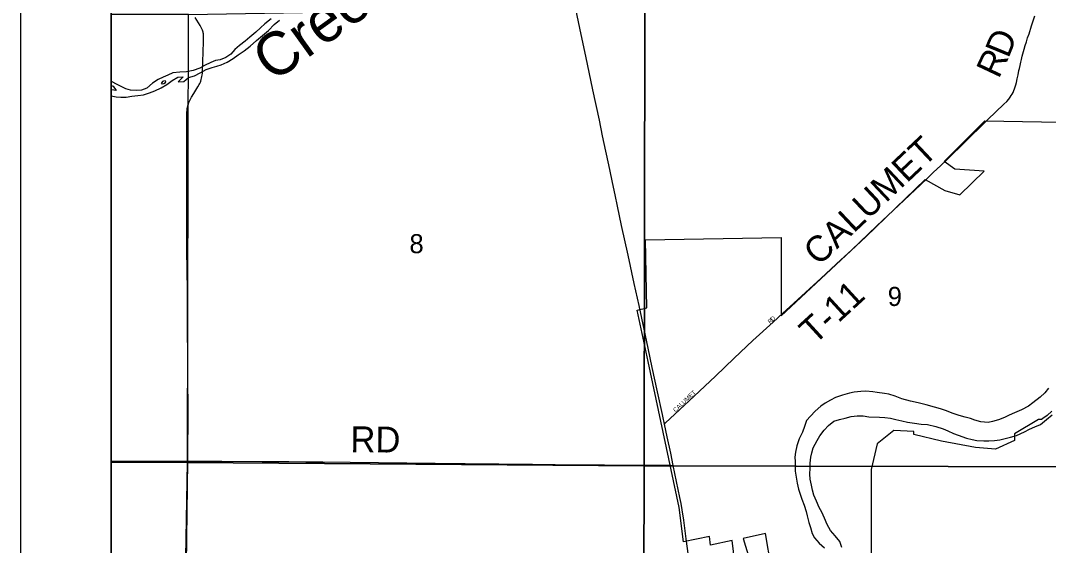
# Model space of a CAD drawing. Extents: x 0 to 680, y 0 to 440.
# Drawn here: x 341.54 to 381.29, y 256.36 to 276.66 of the extents above; entities that cross this region are included whole.
import ezdxf

# ---------------------------------------------------------------- set-up
doc = ezdxf.new("R2010")
doc.units = 0
for name, color, linetype in [('GM_X_Adjacent_County', 7, 'Continuous'), ('GM_X_City_Street', 7, 'Continuous'), ('GM_X_City_Street_Text', 7, 'Continuous'), ('GM_X_Corporation', 7, 'Continuous'), ('GM_X_County', 7, 'Continuous'), ('GM_X_Major_River', 7, 'Continuous'), ('GM_X_Minor_River', 7, 'Continuous'), ('GM_X_Minor_River_Text', 7, 'Continuous'), ('GM_X_Section', 7, 'Continuous'), ('GM_X_Section_Text', 7, 'Continuous'), ('GM_X_State_Route', 7, 'Continuous'), ('GM_X_Township', 7, 'Continuous'), ('GM_X_Township_Road', 7, 'Continuous'), ('GM_X_Township_Road_Text', 7, 'Continuous'), ('SH_Data', 7, 'Continuous'), ('SH_Text', 7, 'Continuous')]:
    doc.layers.add(name, color=color, linetype=linetype)

msp = doc.modelspace()

# ---------------------------------------------------------------- linework, layer by layer
at = {"layer": 'GM_X_Adjacent_County'}
msp.add_lwpolyline([(345.039, 415.359), (345.039, 188.757), (345.473, 188.756), (347.217, 188.747), (347.794, 188.745), (350.054, 188.756), (350.975, 188.76), (352.892, 188.767), (353.65, 188.774), (356.075, 188.765), (356.617, 188.773), (363.409, 188.772), (363.555, 188.769), (365.255, 188.724), (373.709, 188.721), (379.321, 188.719), (384.35, 188.722), (392.938, 188.728), (395.267, 188.729), (408.033, 188.58)], dxfattribs=at)
at = {"layer": 'GM_X_City_Street'}
msp.add_lwpolyline([(366.438, 261.053), (366.482, 261.094), (366.842, 261.432), (367.589, 262.133), (368.41, 262.907), (369.141, 263.599), (369.866, 264.283), (370.642, 264.992), (371.026, 265.343)], dxfattribs=at)
at = {"layer": 'GM_X_Corporation'}
for points in [[(369.252, 254.951), (369.056, 256.548), (368.223, 256.371), (368.182, 256.705), (367.176, 256.491), (367.013, 257.823), (366.702, 259.286), (365.811, 263.475), (365.389, 265.463), (365.76, 265.549), (365.714, 268.172), (370.953, 268.263), (370.953, 265.233), (374.232, 268.29), (376.53, 270.509), (377.289, 270.088), (377.866, 269.922), (378.805, 270.829), (377.673, 270.908), (377.254, 271.212), (378.829, 272.787), (382.476, 272.723)], [(381.429, 261.55), (381.249, 261.382), (381.082, 261.265), (381.027, 261.227), (380.904, 261.225), (379.977, 260.668), (379.977, 260.414), (379.242, 260.087), (378.473, 260.141), (377.162, 260.395), (376.082, 260.645), (376.082, 260.768), (375.312, 260.808), (374.672, 260.29), (374.443, 259.301), (374.443, 254.875)], [(370.573, 255.535), (370.347, 256.817), (369.492, 256.62), (370.006, 254.938)]]:
    msp.add_lwpolyline(points, dxfattribs=at)
at = {"layer": 'GM_X_County'}
msp.add_lwpolyline([(345.039, 415.359), (345.039, 188.757), (345.473, 188.756), (347.217, 188.747), (347.794, 188.745), (350.054, 188.756), (350.975, 188.76), (352.892, 188.767), (353.65, 188.774), (356.075, 188.765), (356.617, 188.773), (363.409, 188.772), (363.555, 188.769), (365.255, 188.724), (373.709, 188.721), (379.321, 188.719), (384.35, 188.722), (392.938, 188.728), (395.267, 188.729), (408.033, 188.58)], dxfattribs=at)
at = {"layer": 'GM_X_Major_River'}
for points in [[(381.299, 262.435), (381.154, 262.264), (380.969, 262.095), (380.695, 261.873), (380.517, 261.743), (380.245, 261.609), (379.974, 261.482), (379.771, 261.399), (379.594, 261.31), (379.357, 261.215), (379.127, 261.147), (378.958, 261.117), (378.684, 261.144), (378.45, 261.204), (378.277, 261.268), (378.077, 261.313), (377.844, 261.379), (377.565, 261.48), (377.352, 261.559), (377.112, 261.645), (376.892, 261.711), (376.566, 261.799), (376.306, 261.866), (376.132, 261.903), (375.952, 261.941), (375.625, 262.03), (375.366, 262.13), (375.126, 262.203), (374.952, 262.234), (374.671, 262.274), (374.497, 262.298), (374.236, 262.325), (374.035, 262.316), (373.779, 262.289), (373.604, 262.246), (373.327, 262.166), (373.063, 262.078), (372.866, 261.982), (372.661, 261.86), (372.484, 261.75), (372.265, 261.547), (372.086, 261.364), (371.941, 261.193), (371.854, 260.96), (371.775, 260.734), (371.655, 260.482), (371.561, 260.216), (371.508, 259.969), (371.49, 259.775), (371.492, 259.601), (371.494, 259.406), (371.497, 259.232), (371.532, 259.003), (371.573, 258.767), (371.628, 258.531), (371.69, 258.335), (371.753, 258.153), (371.841, 257.909), (371.929, 257.672), (371.965, 257.497), (372.032, 257.241), (372.088, 257.052), (372.156, 256.822), (372.24, 256.652), (372.422, 256.447), (372.626, 256.268)], [(373.298, 256.276), (373.221, 256.504), (373.05, 256.728), (372.865, 256.938), (372.74, 257.168), (372.63, 257.411), (372.526, 257.647), (372.421, 257.823), (372.317, 258.065), (372.219, 258.308), (372.168, 258.496), (372.124, 258.691), (372.08, 258.92), (372.07, 259.114), (372.073, 259.349), (372.082, 259.543), (372.106, 259.77), (372.141, 259.937), (372.198, 260.131), (372.349, 260.41), (372.453, 260.596), (372.617, 260.822), (372.78, 260.994), (372.991, 261.158), (373.213, 261.229), (373.436, 261.286), (373.665, 261.35), (373.893, 261.373), (374.121, 261.37), (374.349, 261.327), (374.758, 261.321), (374.959, 261.305), (375.187, 261.275), (375.395, 261.231), (375.629, 261.181), (375.836, 261.131), (376.118, 261.087), (376.365, 261.05), (376.613, 261.033), (376.941, 260.955), (377.222, 260.864), (377.402, 260.794), (377.622, 260.684), (377.802, 260.621), (378.13, 260.502), (378.337, 260.452), (378.524, 260.416), (378.793, 260.405), (378.987, 260.409), (379.202, 260.42), (379.417, 260.443), (379.613, 260.494), (379.828, 260.545), (380.051, 260.615), (380.361, 260.758), (380.557, 260.849), (380.767, 260.947), (380.983, 261.031), (381.22, 261.228), (381.438, 261.413)]]:
    msp.add_lwpolyline(points, dxfattribs=at)
at = {"layer": 'GM_X_Minor_River'}
msp.add_line((345.058, 273.976), (345.039, 273.974), dxfattribs=at)
for points in [[(351.232, 276.728), (350.992, 276.539), (350.814, 276.382), (350.635, 276.212), (350.403, 276.016), (350.231, 275.866), (350.012, 275.69), (349.821, 275.541), (349.669, 275.363), (349.477, 275.227), (349.26, 275.138), (349.079, 275.115), (348.895, 275.033), (348.658, 274.917), (348.467, 274.815), (348.217, 274.733), (347.961, 274.679), (347.705, 274.665), (347.423, 274.638), (347.24, 274.548), (347.056, 274.466), (346.866, 274.376), (346.648, 274.234), (346.422, 274.045), (346.212, 273.969), (346.004, 273.954), (345.796, 273.965), (345.616, 274.023), (345.424, 274.115), (345.251, 274.206), (345.079, 274.291), (345.039, 274.306)], [(345.039, 273.753), (345.233, 273.704), (345.413, 273.693), (345.622, 273.701), (345.837, 273.73), (346.073, 273.764), (346.295, 273.793), (346.532, 273.861), (346.735, 273.943), (346.972, 274.052), (347.191, 274.187), (347.402, 274.343), (347.62, 274.466), (347.828, 274.481), (347.629, 274.285), (347.858, 274.306), (348.029, 274.456), (348.272, 274.524), (348.483, 274.633), (348.715, 274.769), (348.951, 274.85), (349.134, 274.893), (349.303, 274.949), (349.533, 275.051), (349.765, 275.187), (349.956, 275.336), (350.188, 275.492), (350.421, 275.674), (350.661, 275.89), (350.894, 276.079), (351.127, 276.281), (351.347, 276.504), (351.553, 276.673)], [(347.127, 274.33), (347.066, 274.318), (347.026, 274.305), (346.977, 274.226), (347.017, 274.212), (347.084, 274.23), (347.145, 274.262), (347.153, 274.302)], [(347.153, 274.302), (347.127, 274.33)], [(345.039, 274.151), (345.115, 274.122), (345.239, 273.952), (345.058, 273.976)]]:
    msp.add_lwpolyline(points, dxfattribs=at)
at = {"layer": 'GM_X_Section'}
for points in [[(348.037, 276.897), (365.687, 277.203), (365.663, 259.44), (347.996, 259.569)], [(365.687, 277.203), (383.405, 277.313), (383.298, 259.399), (365.663, 259.44)], [(345.039, 276.895), (345.039, 259.579), (347.996, 259.569), (348.037, 276.897)], [(345.039, 259.579), (345.039, 241.25), (347.667, 241.224), (347.996, 259.569)], [(347.996, 259.569), (365.663, 259.44), (365.612, 241.297), (347.667, 241.224)], [(365.663, 259.44), (383.298, 259.399), (383.315, 241.642), (365.612, 241.297)]]:
    msp.add_lwpolyline(points, close=True, dxfattribs=at)
at = {"layer": 'GM_X_State_Route'}
for points in [[(365.463, 265.636), (365.275, 266.488), (365.033, 267.587), (364.785, 268.737), (364.63, 269.479), (364.536, 269.915), (364.434, 270.392), (364.327, 270.905), (364.052, 272.199), (363.924, 272.809), (363.674, 273.984), (363.404, 275.282), (363.224, 276.119), (363.017, 277.097)], [(366.361, 261.416), (366.174, 262.298), (365.973, 263.241), (365.813, 263.992), (365.463, 265.636)], [(367.285, 256.614), (367.189, 257.329), (367.125, 257.738), (367.084, 257.986), (367.039, 258.217), (366.782, 259.455), (366.684, 259.926), (366.543, 260.557), (366.438, 261.053), (366.373, 261.361), (366.361, 261.416)], [(367.799, 252.693), (367.727, 253.234), (367.637, 253.916), (367.506, 254.937), (367.373, 255.952), (367.285, 256.614)]]:
    msp.add_lwpolyline(points, dxfattribs=at)
at = {"layer": 'GM_X_Township'}
msp.add_lwpolyline([(345.039, 295.02), (345.039, 188.757), (345.473, 188.756), (347.217, 188.747), (347.794, 188.745), (350.054, 188.756), (350.975, 188.76), (352.892, 188.767), (353.65, 188.774), (356.075, 188.765), (356.617, 188.773), (363.409, 188.772), (363.555, 188.769), (365.255, 188.724), (373.709, 188.721), (379.321, 188.719), (384.35, 188.722), (392.938, 188.728), (395.267, 188.729), (408.033, 188.58), (418.103, 188.464), (418.29, 277.524)], dxfattribs=at)
at = {"layer": 'GM_X_Township_Road'}
for points in [[(347.976, 268.004), (347.975, 268.551), (347.974, 269.953), (347.967, 271.004), (347.968, 272.329), (347.966, 272.922), (347.968, 273.015), (347.973, 273.119), (347.979, 273.186), (347.988, 273.258), (347.997, 273.308), (348.019, 273.404), (348.048, 273.485), (348.072, 273.542), (348.15, 273.7), (348.236, 273.845), (348.399, 274.098), (348.447, 274.181), (348.472, 274.227), (348.493, 274.277), (348.509, 274.32), (348.528, 274.379), (348.54, 274.427), (348.555, 274.499), (348.562, 274.55), (348.57, 274.63), (348.573, 274.675), (348.619, 275.843), (348.619, 275.963), (348.617, 276.047), (348.616, 276.09), (348.612, 276.136), (348.61, 276.152), (348.604, 276.19), (348.601, 276.206), (348.592, 276.244), (348.578, 276.285), (348.556, 276.339), (348.527, 276.392), (348.482, 276.467), (348.292, 276.781)], [(378.953, 272.827), (379.572, 273.424), (379.684, 273.535), (379.759, 273.623), (379.812, 273.694), (379.856, 273.757), (379.89, 273.814), (379.923, 273.879), (379.958, 273.955), (379.984, 274.018), (380.01, 274.097), (380.032, 274.173), (380.056, 274.26), (380.089, 274.405), (380.124, 274.567), (380.154, 274.722), (380.174, 274.809), (380.201, 274.927), (380.23, 275.049), (380.254, 275.158), (380.283, 275.278), (380.306, 275.373), (380.333, 275.466), (380.356, 275.55), (380.398, 275.693), (380.439, 275.833), (380.489, 275.989), (380.541, 276.147), (380.641, 276.453), (380.77, 276.838)], [(377.362, 271.275), (378.848, 272.729), (378.953, 272.827)], [(376.623, 270.582), (376.834, 270.78), (377.126, 271.053), (377.362, 271.275)], [(371.026, 265.343), (371.443, 265.728), (372.501, 266.697), (373.263, 267.405), (373.673, 267.785), (374.659, 268.717), (375.508, 269.524), (376.345, 270.311), (376.623, 270.582)], [(348.007, 259.616), (348.015, 261.664), (348.006, 262.759), (348.003, 263.744), (347.999, 264.664), (347.992, 266.219), (347.981, 266.986), (347.976, 267.807), (347.976, 268.004)], [(345.039, 259.626), (345.594, 259.623), (348.007, 259.616)], [(347.914, 252.86), (347.926, 253.644), (348.007, 259.616)], [(348.007, 259.616), (349.32, 259.612), (350.877, 259.601), (351.194, 259.601), (351.343, 259.601), (351.629, 259.601), (351.912, 259.599), (352.568, 259.594), (352.776, 259.591), (353.225, 259.587), (354.291, 259.578), (357.569, 259.534), (357.996, 259.531), (358.248, 259.532), (358.74, 259.527), (361.336, 259.503), (362.212, 259.494), (363.427, 259.48), (364.128, 259.474), (366.693, 259.456), (366.782, 259.455)]]:
    msp.add_lwpolyline(points, dxfattribs=at)
at = {"layer": 'SH_Data'}
for p, q in [((341.539, 418.859), (341.539, 173.859)), ((345.039, 415.359), (345.039, 177.359))]:
    msp.add_line(p, q, dxfattribs=at)
at = {"layer": 'SH_Text'}
for points in [[(345.039, 415.359), (583.039, 415.359), (583.039, 177.359), (345.039, 177.359)], [(345.039, 415.359), (345.039, 177.359), (583.038, 177.359), (583.038, 415.359)]]:
    msp.add_lwpolyline(points, close=True, dxfattribs=at)

# ---------------------------------------------------------------- texts
at = {"layer": 'GM_X_City_Street_Text'}
for s, height, rotation, p in [('D', 0.167, 44.3233, (370.632, 265.017)), ('R', 0.167, 41.4258, (370.527, 264.923)), ('CALUMET', 0.1669, 43.1923, (366.868, 261.5))]:
    msp.add_text(s, height=height, rotation=rotation, dxfattribs=at).set_placement(p)
at = {"layer": 'GM_X_Minor_River_Text'}
msp.add_text('Creek', height=1.6686, rotation=35.6507, dxfattribs=at).set_placement((351.295, 274.235))
at = {"layer": 'GM_X_Section_Text'}
for s, p in [('8', (356.58, 267.661)), ('9', (375.078, 265.62))]:
    msp.add_text(s, height=0.738, rotation=0, dxfattribs=at).set_placement(p)
at = {"layer": 'GM_X_Township_Road_Text'}
for s, height, rotation, p in [('D', 1.001, 67.6674, (379.741, 275.172)), ('R', 1.001, 64.828, (379.37, 274.379)), ('CALUMET', 1.0014, 43.3182, (372.406, 267.139)), ('T-11', 1.0014, 42.5097, (372.236, 264.089)), ('RD', 1.0014, 359.5106, (354.292, 259.964))]:
    msp.add_text(s, height=height, rotation=rotation, dxfattribs=at).set_placement(p)

doc.saveas('drawing.dxf')
